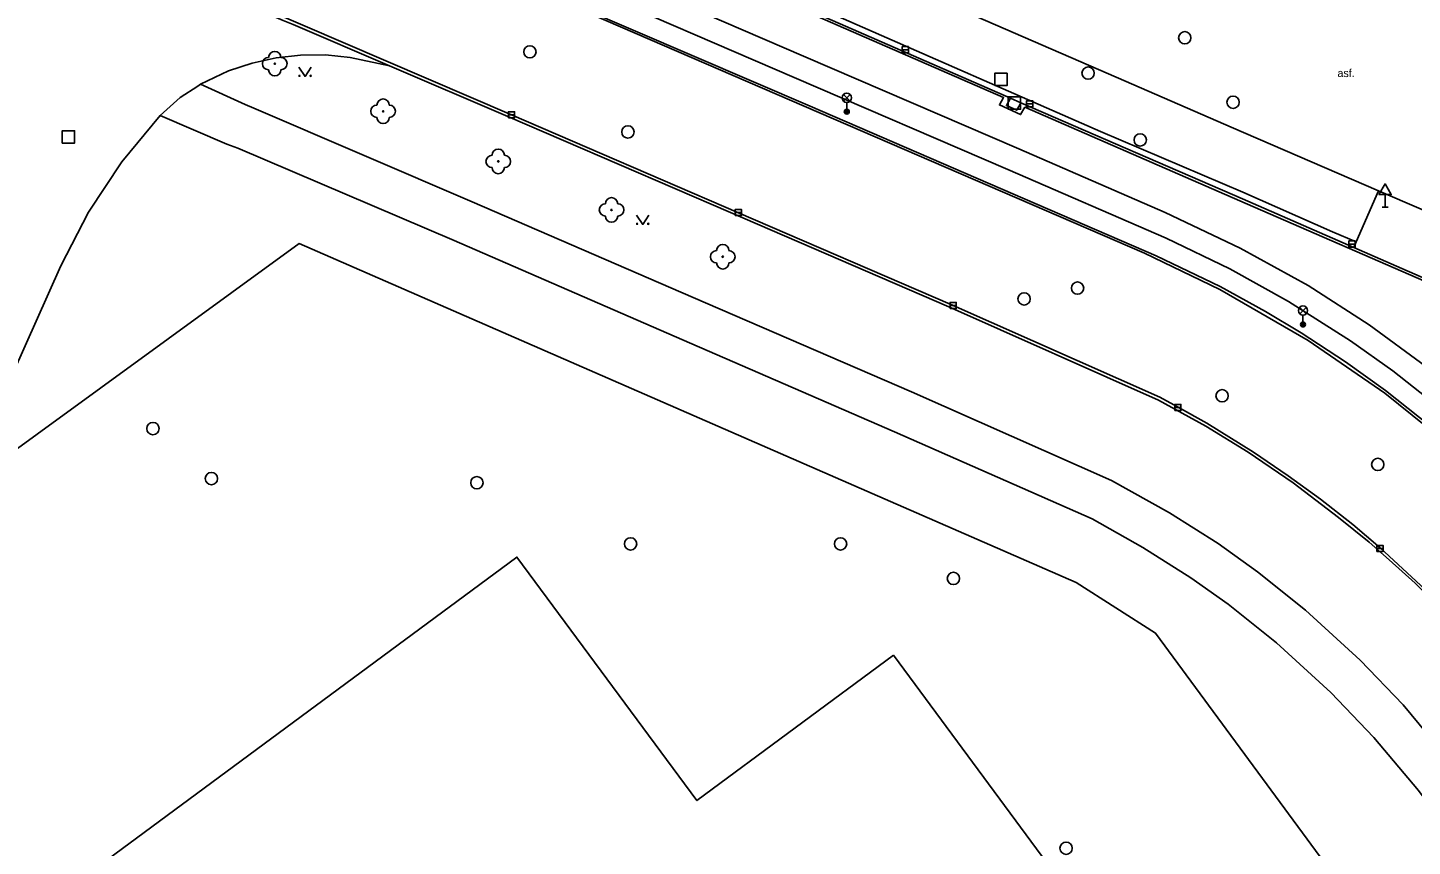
# Model space of a CAD drawing. Extents: x -596024 to -594475, y -1163820 to -1161957.
# Drawn here: x -594681.4 to -594569, y -1162691.2 to -1162624.8 of the extents above; entities that cross this region are included whole.
import ezdxf

# ---------------------------------------------------------------- set-up
doc = ezdxf.new("R2010")
doc.units = 0
for name, color, linetype in [('Level 10', 7, 'Continuous'), ('Level 11', 7, 'Continuous'), ('Level 22', 7, 'Continuous'), ('Level 26', 7, 'Continuous'), ('Level 27', 7, 'Continuous'), ('Level 33', 7, 'Continuous'), ('Level 34', 7, 'Continuous'), ('Level 36', 7, 'Continuous'), ('Level 40', 7, 'Continuous'), ('Level 5', 7, 'Continuous'), ('Level 51', 7, 'Continuous'), ('Level 7', 7, 'Continuous')]:
    doc.layers.add(name, color=color, linetype=linetype)

msp = doc.modelspace()

# ---------------------------------------------------------------- linework, layer by layer
at = {"layer": 'Level 10'}
for points in [[(-594548, -1162678.06), (-594551.53, -1162673.38), (-594555.77, -1162668.36), (-594561.01, -1162662.87), (-594566.52, -1162657.88), (-594571.13, -1162654.23), (-594574.38, -1162651.9), (-594577.98, -1162649.53), (-594580.87, -1162647.82), (-594584.56, -1162645.79), (-594589.75, -1162643.3), (-594617.86, -1162631.14), (-594655.6, -1162614.88), (-594693.79, -1162598.45), (-594730.07, -1162582.86), (-594748.26, -1162574.97), (-594759.55, -1162570.1)], [(-594573.51, -1162642.16), (-594575.44, -1162641.33), (-594582.72, -1162638.13), (-594594.27, -1162633.18), (-594615.14, -1162624.05), (-594634.95, -1162615.44), (-594635.63, -1162615.15)], [(-594661.21, -1162627.21), (-594663.17, -1162627.64)], [(-594659.25, -1162626.98), (-594661.21, -1162627.21)], [(-594657.22, -1162626.97), (-594659.25, -1162626.98)], [(-594655.22, -1162627.17), (-594657.22, -1162626.97)], [(-594652.02, -1162627.85), (-594655.22, -1162627.17)], [(-594665.09, -1162628.27), (-594667.35, -1162629.35)], [(-594663.17, -1162627.64), (-594665.09, -1162628.27)], [(-594589.56, -1162655), (-594606.59, -1162647.43), (-594624.32, -1162639.78), (-594642.41, -1162631.97), (-594652.02, -1162627.85)], [(-594667.59, -1162629.51), (-594669.02, -1162630.43)], [(-594667.35, -1162629.35), (-594667.59, -1162629.51)], [(-594669.02, -1162630.43), (-594670.64, -1162631.88)], [(-594571.69, -1162638.02), (-594573.51, -1162642.16)], [(-594553.81, -1162645.71), (-594571.69, -1162638.02)], [(-594570.84, -1162667.98), (-594572.46, -1162666.54), (-594574.94, -1162664.54), (-594578.63, -1162661.73), (-594582.29, -1162659.23), (-594585.72, -1162657.12), (-594589.56, -1162655)], [(-594559.63, -1162680.02), (-594561.64, -1162677.54), (-594564.05, -1162674.71), (-594566.59, -1162672.03), (-594568.73, -1162669.88), (-594570.84, -1162667.98)]]:
    msp.add_lwpolyline(points, dxfattribs=at)
at = {"layer": 'Level 11'}
for points in [[(-594542.36, -1162683.09), (-594546.18, -1162677.82), (-594549.97, -1162672.7), (-594554.75, -1162667.32), (-594558.7, -1162663.05), (-594564.46, -1162657.42), (-594570.53, -1162652.64), (-594573.97, -1162650.2), (-594579, -1162646.99), (-594583.78, -1162644.35), (-594588.95, -1162641.84), (-594601.81, -1162636.27), (-594619.14, -1162628.81), (-594636.99, -1162621.1), (-594655.59, -1162613.05), (-594659.54, -1162611.44), (-594673.3, -1162605.5), (-594674.42, -1162604.99), (-594693.09, -1162596.94), (-594710.64, -1162589.4), (-594729.39, -1162581.33), (-594747.52, -1162573.55), (-594761.45, -1162567.56), (-594763.07, -1162566.87)], [(-594731.51, -1162593.45), (-594712.68, -1162601.48), (-594679.47, -1162615.75), (-594642.1, -1162631.83), (-594623.67, -1162639.79), (-594606.49, -1162647.2), (-594589.45, -1162654.77), (-594588.02, -1162655.56), (-594585.64, -1162656.89), (-594581.84, -1162659.23), (-594579.03, -1162661.16), (-594576.4, -1162663.05), (-594573.78, -1162665.11), (-594571.57, -1162667), (-594567.19, -1162671.07), (-594563.84, -1162674.57), (-594561.52, -1162677.27), (-594559.43, -1162679.87), (-594556.51, -1162684.02), (-594555.42, -1162685.84), (-594554.69, -1162687.42), (-594554.12, -1162689.12), (-594553.77, -1162690.82), (-594553.58, -1162692.52)], [(-594693.86, -1162598.64), (-594637.82, -1162622.71), (-594590.7, -1162643.08), (-594584.59, -1162646.01), (-594577.42, -1162650.16), (-594571.18, -1162654.43), (-594565.76, -1162658.8), (-594561.7, -1162662.7), (-594556.25, -1162668.32), (-594551.36, -1162673.9), (-594538.88, -1162690.77), (-594526.2, -1162708.04)], [(-594652.02, -1162627.85), (-594659.84, -1162624.49), (-594660.66, -1162624.17), (-594679.57, -1162615.98), (-594689.87, -1162611.56)], [(-594571.69, -1162638.02), (-594583.65, -1162632.85), (-594592.19, -1162629.13), (-594613.41, -1162619.91), (-594633.83, -1162611.01)], [(-594635.92, -1162615.8), (-594637.28, -1162618.91), (-594636.24, -1162619.36), (-594618.39, -1162627.06), (-594600.91, -1162634.59), (-594589.03, -1162639.76), (-594582.92, -1162642.66), (-594577.41, -1162645.7), (-594572.45, -1162648.89), (-594567.89, -1162652.24), (-594563.28, -1162655.94), (-594556.2, -1162662.93), (-594552.13, -1162667.34), (-594548.42, -1162671.61), (-594539, -1162684.2)], [(-594601.58, -1162630.48), (-594615.42, -1162624.44), (-594635.81, -1162615.57)], [(-594667.35, -1162629.35), (-594663.74, -1162631), (-594663.02, -1162631.3), (-594645.31, -1162638.91), (-594627.34, -1162646.67), (-594609.62, -1162654.34), (-594593.39, -1162661.54), (-594588.68, -1162664.16), (-594584.73, -1162666.66), (-594581.53, -1162668.96), (-594577.63, -1162672.07), (-594573.19, -1162676.11), (-594569.7, -1162679.76), (-594565.65, -1162684.62), (-594557.42, -1162695.76)], [(-594600.74, -1162630.86), (-594601.08, -1162631.46), (-594601.92, -1162631.08), (-594601.58, -1162630.48)], [(-594601.58, -1162630.48), (-594600.74, -1162630.86)], [(-594670.64, -1162631.88), (-594673.75, -1162635.66), (-594676.45, -1162639.74), (-594678.7, -1162644.09), (-594682.59, -1162652.85), (-594686.11, -1162661.76), (-594659.34, -1162642.29), (-594596.26, -1162669.81), (-594589.8, -1162673.93), (-594574.99, -1162694.04), (-594580.8, -1162698.01), (-594586.48, -1162701.88), (-594590, -1162704.28)], [(-594560.26, -1162697.84), (-594568.46, -1162686.71), (-594572.09, -1162682.41), (-594575.57, -1162678.76), (-594579.99, -1162674.71), (-594583.91, -1162671.58), (-594586.93, -1162669.45), (-594590.83, -1162666.97), (-594594.96, -1162664.65), (-594611.01, -1162657.58), (-594628.89, -1162649.8), (-594646.77, -1162642.04), (-594664.34, -1162634.54), (-594665.21, -1162634.23), (-594670.64, -1162631.88)], [(-594582.75, -1162638.66), (-594600.74, -1162630.86)], [(-594573.51, -1162642.16), (-594573.7, -1162642.62), (-594582.75, -1162638.66)], [(-594573.7, -1162642.62), (-594556.01, -1162650.36)]]:
    msp.add_lwpolyline(points, dxfattribs=at)
at = {"layer": 'Level 22'}
for centre in [(-594661.33, -1162627.68), (-594652.53, -1162631.55), (-594643.18, -1162635.62), (-594633.98, -1162639.56), (-594624.95, -1162643.36)]:
    msp.add_circle(centre, 0.05, dxfattribs=at)
for centre, start, end in [((-594661.83, -1162627.68), 90, 270), ((-594661.33, -1162627.18), 0, 180), ((-594660.83, -1162627.68), 270, 90), ((-594661.33, -1162628.18), 180, 0), ((-594652.53, -1162631.05), 0, 180), ((-594653.03, -1162631.55), 90, 270), ((-594652.03, -1162631.55), 270, 90), ((-594652.53, -1162632.05), 180, 0), ((-594643.68, -1162635.62), 90, 270), ((-594643.18, -1162635.12), 0, 180), ((-594642.68, -1162635.62), 270, 90), ((-594643.18, -1162636.12), 180, 0), ((-594633.98, -1162639.06), 0, 180), ((-594634.48, -1162639.56), 90, 270), ((-594633.48, -1162639.56), 270, 90), ((-594633.98, -1162640.06), 180, 0), ((-594625.45, -1162643.36), 90, 270), ((-594624.95, -1162642.86), 0, 180), ((-594624.45, -1162643.36), 270, 90), ((-594624.95, -1162643.86), 180, 0)]:
    msp.add_arc(centre, 0.5, start, end, dxfattribs=at)
at = {"layer": 'Level 26'}
for points in [[(-594602.86, -1162629.46), (-594601.86, -1162629.46), (-594601.86, -1162628.46), (-594602.86, -1162628.46)], [(-594601.77, -1162631.38), (-594600.77, -1162631.38), (-594600.77, -1162630.38), (-594601.77, -1162630.38)], [(-594678.59, -1162634.13), (-594677.59, -1162634.13), (-594677.59, -1162633.13), (-594678.59, -1162633.13)]]:
    msp.add_lwpolyline(points, close=True, dxfattribs=at)
at = {"layer": 'Level 27'}
for p, q in [((-594610.37, -1162626.55), (-594609.87, -1162626.55)), ((-594642.35, -1162631.83), (-594641.85, -1162631.83)), ((-594600.28, -1162630.94), (-594599.78, -1162630.94)), ((-594623.93, -1162639.77), (-594623.43, -1162639.77)), ((-594574.1, -1162642.33), (-594573.6, -1162642.33)), ((-594606.49, -1162647.32), (-594605.99, -1162647.32)), ((-594588.25, -1162655.61), (-594587.75, -1162655.61)), ((-594571.83, -1162667.06), (-594571.33, -1162667.06))]:
    msp.add_line(p, q, dxfattribs=at)
for points in [[(-594610.37, -1162626.8), (-594609.87, -1162626.8), (-594609.87, -1162626.3), (-594610.37, -1162626.3)], [(-594600.28, -1162631.19), (-594599.78, -1162631.19), (-594599.78, -1162630.69), (-594600.28, -1162630.69)], [(-594642.35, -1162632.08), (-594641.85, -1162632.08), (-594641.85, -1162631.58), (-594642.35, -1162631.58)], [(-594623.93, -1162640.02), (-594623.43, -1162640.02), (-594623.43, -1162639.52), (-594623.93, -1162639.52)], [(-594574.1, -1162642.58), (-594573.6, -1162642.58), (-594573.6, -1162642.08), (-594574.1, -1162642.08)], [(-594606.49, -1162647.57), (-594605.99, -1162647.57), (-594605.99, -1162647.07), (-594606.49, -1162647.07)], [(-594588.25, -1162655.86), (-594587.75, -1162655.86), (-594587.75, -1162655.36), (-594588.25, -1162655.36)], [(-594571.83, -1162667.31), (-594571.33, -1162667.31), (-594571.33, -1162666.81), (-594571.83, -1162666.81)]]:
    msp.add_lwpolyline(points, close=True, dxfattribs=at)
for centre in [(-594587.43, -1162625.58), (-594640.61, -1162626.72), (-594595.28, -1162628.45), (-594583.51, -1162630.82), (-594632.65, -1162633.23), (-594591.05, -1162633.88), (-594600.48, -1162646.79), (-594596.14, -1162645.91), (-594584.4, -1162654.65), (-594671.22, -1162657.32), (-594571.76, -1162660.23), (-594666.48, -1162661.38), (-594644.92, -1162661.71), (-594632.43, -1162666.68), (-594615.38, -1162666.68), (-594606.22, -1162669.49), (-594597.07, -1162691.4)]:
    msp.add_circle(centre, 0.5, dxfattribs=at)
at = {"layer": 'Level 33'}
for p, q in [((-594615.14, -1162630.72), (-594614.61, -1162630.19)), ((-594615.14, -1162630.19), (-594614.61, -1162630.72)), ((-594614.88, -1162630.83), (-594614.88, -1162631.58)), ((-594578.09, -1162648), (-594577.56, -1162647.47)), ((-594578.09, -1162647.47), (-594577.56, -1162648)), ((-594577.83, -1162648.11), (-594577.83, -1162648.86))]:
    msp.add_line(p, q, dxfattribs=at)
for centre, radius in [((-594614.88, -1162630.45), 0.375), ((-594614.88, -1162631.58), 0.2), ((-594614.88, -1162631.58), 0.145), ((-594614.88, -1162631.58), 0.0876), ((-594577.83, -1162647.73), 0.375), ((-594577.83, -1162648.86), 0.2), ((-594577.83, -1162648.86), 0.145), ((-594577.83, -1162648.86), 0.0876)]:
    msp.add_circle(centre, radius, dxfattribs=at)
at = {"layer": 'Level 34'}
for p, q in [((-594571.16, -1162638.31), (-594571.16, -1162639.33)), ((-594571.41, -1162639.33), (-594570.91, -1162639.33))]:
    msp.add_line(p, q, dxfattribs=at)
msp.add_lwpolyline([(-594571.66, -1162638.31), (-594570.66, -1162638.31), (-594571.16, -1162637.45)], close=True, dxfattribs=at)
at = {"layer": 'Level 36'}
for points in [[(-594659.37, -1162627.97), (-594658.87, -1162628.72), (-594658.37, -1162627.97)], [(-594631.95, -1162639.99), (-594631.45, -1162640.74), (-594630.95, -1162639.99)]]:
    msp.add_lwpolyline(points, dxfattribs=at)
for centre in [(-594659.32, -1162628.67), (-594658.42, -1162628.67), (-594631.9, -1162640.69), (-594631, -1162640.69)]:
    msp.add_circle(centre, 0.05, dxfattribs=at)
at = {"layer": 'Level 5'}
msp.add_lwpolyline([(-594582.89, -1162713.92), (-594590, -1162704.28), (-594611.08, -1162675.73)], dxfattribs=at)
at = {"layer": 'Level 51'}
msp.add_lwpolyline([(-594700.35, -1162711.11), (-594641.66, -1162667.75), (-594627.05, -1162687.52), (-594611.08, -1162675.73)], dxfattribs=at)
at = {"layer": 'Level 7'}
msp.add_lwpolyline([(-594635.92, -1162615.8), (-594629.63, -1162618.43), (-594602.14, -1162630.44), (-594602.48, -1162631.03), (-594600.76, -1162631.82), (-594600.41, -1162631.22), (-594581.9, -1162639.29), (-594567.2, -1162645.66), (-594556.07, -1162650.48), (-594556.01, -1162650.36), (-594553.81, -1162645.71)], dxfattribs=at)

# ---------------------------------------------------------------- texts
at = {"layer": 'Level 40'}
msp.add_text('asf.', height=0.65, dxfattribs=at).set_placement((-594575.03, -1162628.77))

doc.saveas('drawing.dxf')
